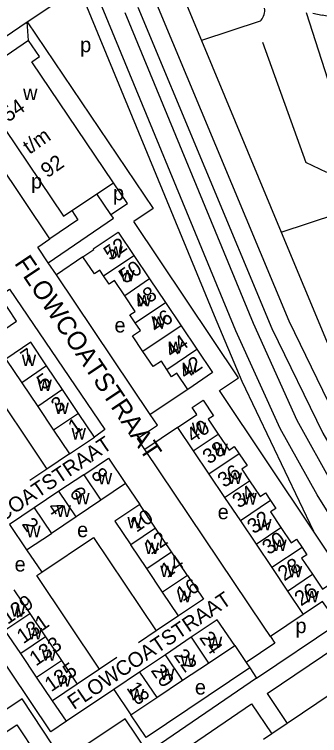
# Model space of a CAD drawing. Extents: x 158356 to 159894, y 383831 to 385260.
# Drawn here: x 159192 to 159274, y 384580.8 to 384774.6 of the extents above; entities that cross this region are included whole.
import ezdxf

# ---------------------------------------------------------------- set-up
doc = ezdxf.new("R2010")
doc.units = 0
for name, color, linetype in [('BLT_Basislijn', 7, 'Continuous'), ('BLT_Bebouwing', 7, 'Continuous'), ('BLT_Centroide', 7, 'Continuous'), ('BLT_Huisnummer', 7, 'Continuous'), ('BLT_Huisnummer_ tussenligend', 7, 'Continuous'), ('BLT_Huisnummer_reeks', 7, 'Continuous'), ('BLT_Onderverdeling_panden', 7, 'Continuous'), ('BLT_Straatnaam', 7, 'Continuous'), ('BLT_Straatnaam_verkleind', 7, 'Continuous'), ('BLT_Vlakafsluiter', 7, 'Continuous')]:
    doc.layers.add(name, color=color, linetype=linetype)

msp = doc.modelspace()

# ---------------------------------------------------------------- linework, layer by layer
at = {"layer": 'BLT_Basislijn'}
for p, q in [((159270.42, 384775.13), (159278.64, 384749.24)), ((159165.33, 384752.25), (159195.44, 384772.62)), ((159258.01, 384772.76), (159242.25, 384767.58)), ((159242.25, 384767.58), (159263.67, 384716.09)), ((159258.67, 384767.16), (159270.27, 384734.75)), ((159201.53, 384714.24), (159174.99, 384753.62)), ((159275.96, 384732.1), (159270.27, 384734.75)), ((159217.94, 384720.81), (159214.18, 384726.37)), ((159263.67, 384716.09), (159290.42, 384724.92)), ((159198.27, 384712.03), (159201.53, 384714.24)), ((159201.06, 384707.87), (159198.27, 384712.03)), ((159210.41, 384709.41), (159203.28, 384704.57)), ((159203.28, 384704.57), (159201.06, 384707.87)), ((159228.48, 384667.06), (159203.28, 384704.57)), ((159238.56, 384673.83), (159228.48, 384667.06)), ((159272.34, 384635.69), (159247.08, 384673.53)), ((159230.41, 384664.19), (159228.48, 384667.06)), ((159225.05, 384660.59), (159230.41, 384664.19)), ((159235.82, 384663.6), (159227, 384657.67)), ((159216.3, 384663.04), (159213.5, 384661.02)), ((159227, 384657.67), (159225.05, 384660.59)), ((159258.91, 384610.18), (159227, 384657.67)), ((159206.83, 384656.53), (159200.71, 384652.42)), ((159200.71, 384652.42), (159196.12, 384649.33)), ((159221.86, 384648.53), (159225.67, 384642.9)), ((159283.03, 384619.67), (159272.34, 384635.69)), ((159195.29, 384630.66), (159199.35, 384624.67)), ((159236.11, 384612.94), (159230.1, 384608.9)), ((159257.08, 384596.26), (159281.32, 384612.62)), ((159230.1, 384608.9), (159225.37, 384605.73)), ((159259.87, 384592.11), (159283.82, 384608.28)), ((159251.21, 384605.01), (159254.25, 384600.47)), ((159219.53, 384601.8), (159214.87, 384598.67)), ((159254.25, 384600.47), (159255.27, 384598.97)), ((159214.87, 384598.67), (159208.88, 384594.64)), ((159255.27, 384598.97), (159257.08, 384596.26)), ((159218.68, 384593.18), (159205.96, 384584.63)), ((159259.87, 384592.11), (159265.31, 384584.02)), ((159205.96, 384584.63), (159202.2, 384590.15)), ((159239.62, 384578.33), (159255.72, 384589.33)), ((159255.72, 384589.33), (159261.16, 384581.23))]:
    msp.add_line(p, q, dxfattribs=at)
for points in [[(159078.95, 384989.43), (159096.2, 384978.92), (159116.42, 384963.88), (159133.76, 384948.84), (159152.75, 384928.69), (159175.27, 384898.83), (159191.66, 384869.8), (159265.75, 384692.27), (159279.24, 384664.38), (159294.85, 384637.65), (159324.9, 384593.77), (159342.37, 384573.46), (159351.56, 384565.34), (159355.82, 384562.28)], [(159152.96, 384940.11), (159158.01, 384934.39), (159169.6, 384919.59), (159180.4, 384904.21), (159193.4, 384881.61), (159203.52, 384860.74), (159242.25, 384767.58)], [(159292.78, 384615.33), (159285.44, 384626.08), (159273.33, 384645.49), (159263.43, 384663.32), (159251.53, 384689.59), (159213.29, 384782.3)], [(159195.44, 384772.62), (159205.81, 384779.58), (159209.65, 384780.98)], [(159209.65, 384780.98), (159245.68, 384693.66), (159253.11, 384675.99), (159272.34, 384635.69)], [(159225.16, 384776.55), (159261.19, 384690.21), (159274.82, 384662.03), (159290.62, 384634.97), (159320.93, 384590.72)], [(159258.01, 384772.76), (159258.3, 384773.06), (159258.55, 384773.4), (159258.77, 384773.76), (159258.96, 384774.16), (159259.1, 384774.57), (159259.19, 384774.99), (159259.24, 384775.41), (159259.25, 384775.84), (159259.21, 384776.25)], [(159221.67, 384775.1), (159256.12, 384691.58), (159267.9, 384665.57), (159277.64, 384648.03), (159289.62, 384628.82), (159296.91, 384618.16)], [(159195.44, 384772.62), (159229.32, 384722.45), (159224.07, 384718.92)], [(159217.94, 384720.81), (159222.38, 384723.8), (159218.63, 384729.35)], [(159207.44, 384721.85), (159209.07, 384719.39), (159201.53, 384714.24)], [(159201.06, 384707.87), (159218.6, 384719.83), (159217.94, 384720.81)], [(159247.08, 384673.53), (159252.18, 384676.95), (159224.07, 384718.92)], [(159263.67, 384716.09), (159275.85, 384686.88), (159281.11, 384675.39), (159288.01, 384662.09), (159292.49, 384654.69)], [(159187.99, 384698.93), (159190.67, 384700.75), (159216.3, 384663.04)], [(159170.09, 384668.24), (159183.85, 384677.49), (159200.71, 384652.42)], [(159199.35, 384624.67), (159213.23, 384633.99), (159230.1, 384608.9)], [(159214.87, 384598.67), (159198.03, 384623.78), (159199.35, 384624.67)], [(159205.96, 384584.63), (159201.78, 384581.82), (159180.06, 384614.13)], [(159269.59, 384613.36), (159260.76, 384607.42)], [(159260.76, 384607.42), (159258.91, 384610.18)], [(159260.76, 384607.42), (159261.99, 384605.6), (159254.25, 384600.47)], [(159255.27, 384598.97), (159227.38, 384580.23), (159223.27, 384586.34)], [(159257.08, 384596.26), (159227.83, 384576.27), (159221.79, 384585.31), (159205.01, 384574.09), (159194.06, 384590.62), (159174.84, 384577.88), (159165.47, 384592.02), (159160.83, 384588.95)], [(159159.52, 384582.08), (159164.07, 384585.09), (159173.44, 384570.95), (159192.66, 384583.69), (159203.62, 384567.15), (159220.41, 384578.37), (159226.45, 384569.34), (159235.48, 384575.5)]]:
    msp.add_lwpolyline(points, dxfattribs=at)
at = {"layer": 'BLT_Bebouwing'}
for p, q in [((159214.18, 384726.37), (159218.63, 384729.35)), ((159224.11, 384709.8), (159228.34, 384703.5)), ((159228.34, 384703.5), (159232.57, 384697.21)), ((159232.57, 384697.21), (159236.8, 384690.92)), ((159236.8, 384690.92), (159241.02, 384684.62)), ((159204.95, 384673.75), (159200.67, 384680.11)), ((159193.99, 384675.62), (159198.26, 384669.25)), ((159209.23, 384667.38), (159204.95, 384673.75)), ((159198.26, 384669.25), (159202.55, 384662.89)), ((159213.5, 384661.02), (159209.23, 384667.38)), ((159235.82, 384663.6), (159240.04, 384657.32)), ((159202.55, 384662.89), (159206.83, 384656.53)), ((159206.83, 384656.53), (159213.5, 384661.02)), ((159240.04, 384657.32), (159244.26, 384651.04)), ((159210.62, 384650.9), (159203.98, 384646.43)), ((159244.26, 384651.04), (159248.48, 384644.76)), ((159221.86, 384648.53), (159215.22, 384644.06)), ((159203.98, 384646.43), (159197.33, 384641.97)), ((159215.22, 384644.06), (159208.58, 384639.59)), ((159248.48, 384644.76), (159252.71, 384638.48)), ((159229.95, 384636.53), (159225.67, 384642.9)), ((159197.33, 384641.97), (159190.69, 384637.51)), ((159208.58, 384639.59), (159201.93, 384635.13)), ((159252.71, 384638.48), (159256.93, 384632.2)), ((159190.69, 384637.51), (159195.29, 384630.66)), ((159234.22, 384630.16), (159229.95, 384636.53)), ((159195.29, 384630.66), (159201.93, 384635.13)), ((159227.56, 384625.68), (159223.26, 384632.04)), ((159256.93, 384632.2), (159261.15, 384625.92)), ((159238.5, 384623.79), (159234.22, 384630.16)), ((159231.83, 384619.31), (159227.56, 384625.68)), ((159261.15, 384625.92), (159265.37, 384619.64)), ((159191.88, 384619.93), (159196.13, 384613.61)), ((159236.11, 384612.94), (159231.83, 384619.31)), ((159265.37, 384619.64), (159269.59, 384613.36)), ((159196.13, 384613.61), (159200.38, 384607.29)), ((159193.7, 384602.8), (159189.45, 384609.12)), ((159200.38, 384607.29), (159204.63, 384600.97)), ((159239.51, 384607.19), (159232.57, 384602.52)), ((159244.15, 384600.29), (159251.21, 384605.01)), ((159197.95, 384596.48), (159193.7, 384602.8)), ((159232.57, 384602.52), (159225.62, 384597.85)), ((159204.63, 384600.97), (159208.88, 384594.64)), ((159237.19, 384595.64), (159244.15, 384600.29)), ((159225.62, 384597.85), (159218.68, 384593.18)), ((159202.2, 384590.15), (159197.95, 384596.48)), ((159230.23, 384590.99), (159237.19, 384595.64)), ((159208.88, 384594.64), (159202.2, 384590.15)), ((159218.68, 384593.18), (159223.27, 384586.34)), ((159223.27, 384586.34), (159230.23, 384590.99)), ((159265.31, 384584.02), (159261.16, 384581.23)), ((159261.16, 384581.23), (159258.88, 384579.7))]:
    msp.add_line(p, q, dxfattribs=at)
for points in [[(159282.6, 384772.76), (159274.65, 384774.4), (159274.63, 384774.29), (159272.14, 384774.79)], [(159195.82, 384767.54), (159187.97, 384762.25), (159188.06, 384762.11), (159184.56, 384759.74)], [(159218.63, 384729.35), (159196.67, 384761.86), (159198.71, 384763.24), (159195.82, 384767.54)], [(159184.56, 384759.74), (159187.03, 384755.98), (159183.02, 384753.29), (159205.18, 384720.33), (159214.18, 384726.37)], [(159210.41, 384709.41), (159213.32, 384711.37), (159213.18, 384711.58), (159219.88, 384716.09)], [(159219.88, 384716.09), (159224.11, 384709.8)], [(159215.98, 384704.34), (159214.96, 384705.85), (159213.48, 384704.85), (159210.41, 384709.41)], [(159221.63, 384699), (159218.88, 384703.08), (159217.46, 384702.13), (159215.98, 384704.34)], [(159185.93, 384687.64), (159192.58, 384692.11), (159187.99, 384698.93)], [(159224.44, 384691.75), (159223.04, 384693.83), (159224.47, 384694.78), (159221.63, 384699)], [(159226.51, 384684.01), (159223.7, 384688.19), (159225.85, 384689.67), (159224.44, 384691.75)], [(159200.67, 384680.11), (159196.4, 384686.48), (159189.71, 384681.98), (159193.99, 384675.62)], [(159232.93, 384679.2), (159231.51, 384681.39), (159229.26, 384679.93), (159226.51, 384684.01)], [(159241.02, 384684.62), (159245.24, 384678.32), (159238.56, 384673.83)], [(159238.56, 384673.83), (159235.63, 384678.18), (159234.21, 384677.22), (159232.93, 384679.2)], [(159235.82, 384663.6), (159241.03, 384667.09), (159239.78, 384668.94), (159242.67, 384670.93), (159245.49, 384666.73), (159244.08, 384665.78), (159246.74, 384661.82)], [(159246.74, 384661.82), (159249.65, 384657.47), (159251.08, 384658.43), (159252.38, 384656.49)], [(159252.38, 384656.49), (159254.52, 384653.34), (159253.09, 384652.38), (159255.18, 384649.25)], [(159210.62, 384650.9), (159217.27, 384655.36), (159221.86, 384648.53)], [(159255.18, 384649.25), (159258.01, 384645.02), (159259.45, 384645.98), (159260.82, 384643.93)], [(159225.67, 384642.9), (159218.97, 384638.39), (159223.26, 384632.04)], [(159260.82, 384643.93), (159262.22, 384641.83), (159260.78, 384640.88), (159263.61, 384636.69)], [(159263.61, 384636.69), (159266.38, 384632.59), (159267.8, 384633.54), (159269.26, 384631.37)], [(159269.26, 384631.37), (159270.59, 384629.38), (159269.15, 384628.47), (159272.06, 384624.13)], [(159238.5, 384623.79), (159242.78, 384617.42), (159236.11, 384612.94)], [(159272.06, 384624.13), (159274.74, 384620.13), (159276.17, 384621.1), (159278.96, 384616.95)], [(159278.96, 384616.95), (159276.08, 384614.97), (159274.77, 384616.86), (159269.59, 384613.36)], [(159251.21, 384605.01), (159246.45, 384611.86), (159239.51, 384607.19)], [(159277.4, 384592.14), (159265.31, 384584.02)]]:
    msp.add_lwpolyline(points, dxfattribs=at)
at = {"layer": 'BLT_Onderverdeling_panden'}
for p, q in [((159215.98, 384704.34), (159224.11, 384709.8)), ((159228.34, 384703.5), (159221.63, 384699)), ((159224.44, 384691.75), (159232.57, 384697.21)), ((159236.8, 384690.92), (159226.51, 384684.01)), ((159232.93, 384679.2), (159241.02, 384684.62)), ((159200.67, 384680.11), (159193.99, 384675.62)), ((159204.95, 384673.75), (159198.26, 384669.25)), ((159209.23, 384667.38), (159202.55, 384662.89)), ((159240.04, 384657.32), (159246.74, 384661.82)), ((159252.38, 384656.49), (159244.26, 384651.04)), ((159210.62, 384650.9), (159215.22, 384644.06)), ((159248.48, 384644.76), (159255.18, 384649.25)), ((159208.58, 384639.59), (159203.98, 384646.43)), ((159260.82, 384643.93), (159252.71, 384638.48)), ((159197.33, 384641.97), (159201.93, 384635.13)), ((159229.95, 384636.53), (159223.26, 384632.04)), ((159256.93, 384632.2), (159263.61, 384636.69)), ((159269.26, 384631.37), (159261.15, 384625.92)), ((159227.56, 384625.68), (159234.22, 384630.16)), ((159238.5, 384623.79), (159231.83, 384619.31)), ((159265.37, 384619.64), (159272.06, 384624.13)), ((159189.45, 384609.12), (159196.13, 384613.61)), ((159200.38, 384607.29), (159193.7, 384602.8)), ((159239.51, 384607.19), (159244.15, 384600.29)), ((159237.19, 384595.64), (159232.57, 384602.52)), ((159197.95, 384596.48), (159204.63, 384600.97)), ((159225.62, 384597.85), (159230.23, 384590.99))]:
    msp.add_line(p, q, dxfattribs=at)
at = {"layer": 'BLT_Vlakafsluiter'}
msp.add_line((159195.82, 384767.54), (159195.44, 384772.62), dxfattribs=at)

# ---------------------------------------------------------------- texts
at = {"layer": 'BLT_Centroide'}
for s, p in [('p', (159209.67, 384764.44)), ('w', (159194.34, 384751.55)), ('p', (159196.49, 384727.82)), ('p', (159218.5, 384724.63)), ('w', (159217.28, 384709.23)), ('w', (159220.44, 384702.85)), ('w', (159224.98, 384696.1)), ('w', (159228.84, 384690.34)), ('e', (159218.89, 384689.11)), ('w', (159233.41, 384683.54)), ('w', (159193.99, 384680.08)), ('w', (159237.19, 384677.91)), ('w', (159198.21, 384673.39)), ('w', (159202.79, 384667.22)), ('w', (159207.36, 384660.35)), ('w', (159239.66, 384661.85)), ('w', (159245.48, 384656.12)), ('w', (159214.42, 384648.31)), ('w', (159249.31, 384648.41)), ('w', (159208.35, 384642.93)), ('w', (159253.25, 384642.86)), ('w', (159203.32, 384639.55)), ('e', (159246.61, 384638.92)), ('w', (159222.36, 384636.49)), ('w', (159257.22, 384635.96)), ('w', (159195.19, 384634.09)), ('e', (159208.85, 384634.11)), ('w', (159227.01, 384629.56)), ('w', (159261.27, 384630.36)), ('e', (159192.07, 384624.87)), ('w', (159231.17, 384623.37)), ('w', (159265.46, 384623.32)), ('w', (159235.7, 384616.63)), ('w', (159269.95, 384616.6)), ('w', (159191.01, 384612.71)), ('p', (159267.5, 384608.32)), ('w', (159195.59, 384606.62)), ('w', (159243.97, 384604.32)), ('w', (159199.34, 384600.89)), ('w', (159236.66, 384599.42)), ('w', (159231.13, 384595.7)), ('w', (159203.44, 384593.96)), ('e', (159240.49, 384591.82)), ('w', (159223, 384590.23))]:
    msp.add_text(s, height=4, dxfattribs=at).set_placement(p)
at = {"layer": 'BLT_Huisnummer'}
for s, rotation, p in [('52', 34.8063, (159217.73, 384708.22)), ('46', 34.8063, (159230.06, 384688.91)), ('7', 34.8063, (159195.44, 384680.24)), ('42', 34.8063, (159237.98, 384676.38)), ('5', 34.8063, (159199.78, 384673.54)), ('1', 34.8063, (159208.19, 384661.51)), ('40', 34.8063, (159239.99, 384659.31)), ('8', 304.8063, (159212.42, 384651.01)), ('34', 34.8063, (159252.31, 384641.71)), ('10', 34.8063, (159224.8, 384635.25)), ('2', 304.8063, (159193.84, 384637.61)), ('30', 34.8063, (159260.32, 384629.2)), ('16', 34.8063, (159237.22, 384616.67)), ('26', 34.8063, (159269, 384615.44)), ('129', 34.8063, (159190.2, 384610.52)), ('24', 304.8063, (159241.53, 384607.09)), ('135', 34.8063, (159201.89, 384592.39)), ('18', 304.8063, (159221.96, 384593.57))]:
    msp.add_text(s, height=4, rotation=rotation, dxfattribs=at).set_placement(p)
at = {"layer": 'BLT_Huisnummer_ tussenligend'}
for s, rotation, p in [('50', 34.8063, (159221.79, 384702.05)), ('48', 34.8063, (159225.78, 384695.16)), ('44', 34.8063, (159234.23, 384682.16)), ('3', 34.8063, (159203.63, 384667.35)), ('38', 34.8063, (159244.3, 384653.56)), ('36', 34.8063, (159248.36, 384647.26)), ('6', 304.8063, (159206.64, 384645.97)), ('4', 304.8063, (159200.71, 384641.99)), ('32', 34.8063, (159256.29, 384634.81)), ('12', 34.8063, (159228.65, 384629.25)), ('14', 34.8063, (159233.05, 384623.02)), ('28', 34.8063, (159264.52, 384622.17)), ('131', 34.8063, (159194.4, 384605.3)), ('133', 34.8063, (159197.79, 384599.32)), ('22', 304.8063, (159234.67, 384602.35)), ('20', 304.8063, (159228.52, 384598.27))]:
    msp.add_text(s, height=4, rotation=rotation, dxfattribs=at).set_placement(p)
at = {"layer": 'BLT_Huisnummer_reeks'}
for s, p in [('54', (159190.35, 384745.51)), ('t/m', (159196.05, 384736.85)), ('92', (159200.84, 384730.5))]:
    msp.add_text(s, height=4, rotation=34.8063, dxfattribs=at).set_placement(p)
at = {"layer": 'BLT_Straatnaam'}
msp.add_text('FLOWCOATSTRAAT', height=5, rotation=303.8882, dxfattribs=at).set_placement((159191.85, 384707.72))
at = {"layer": 'BLT_Straatnaam_verkleind'}
for p in [(159175.91, 384629.42), (159207.99, 384587.64)]:
    msp.add_text('FLOWCOATSTRAAT', height=4, rotation=34, dxfattribs=at).set_placement(p)

doc.saveas('drawing.dxf')
